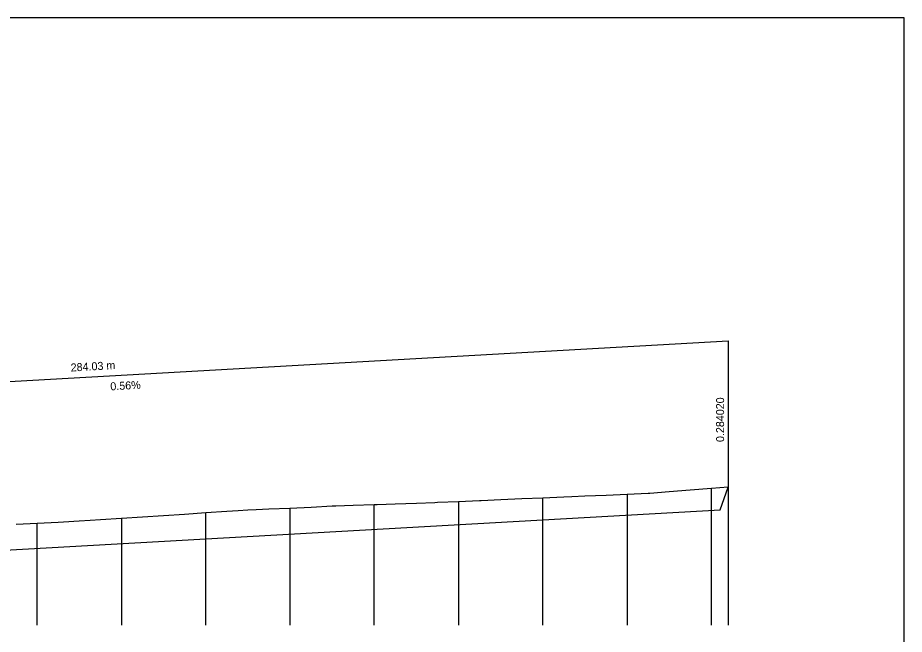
# Model space of a CAD drawing. Extents: x -495905 to -478420, y -1113297 to -1107716.
# Drawn here: x -494568.8 to -494358.5, y -1110160.5 to -1110014.2 of the extents above; entities that cross this region are included whole.
import ezdxf

# ---------------------------------------------------------------- set-up
doc = ezdxf.new("R2010")
doc.units = 0
for name, color, linetype in [('1', 7, 'Continuous'), ('2', 7, 'Continuous'), ('Implicitní', 7, 'Continuous'), ('legenda', 7, 'Continuous')]:
    doc.layers.add(name, color=color, linetype=linetype)

msp = doc.modelspace()

# ---------------------------------------------------------------- linework, layer by layer
at = {"layer": '1'}
for p, q in [((-494429.23, -1110127.56), (-494434.23, -1110127.77)), ((-494424.23, -1110127.34), (-494429.23, -1110127.56)), ((-494419.23, -1110127.12), (-494424.23, -1110127.34)), ((-494424.23, -1110127.34), (-494424.23, -1110154.39)), ((-494418.87, -1110127.11), (-494419.23, -1110127.12)), ((-494414.23, -1110126.75), (-494418.87, -1110127.11)), ((-494409.23, -1110126.36), (-494414.23, -1110126.75)), ((-494404.23, -1110125.96), (-494409.23, -1110126.36)), ((-494400.21, -1110125.65), (-494404.23, -1110125.96)), ((-494404.23, -1110154.39), (-494404.23, -1110125.96)), ((-494400.21, -1110125.65), (-494400.21, -1110154.39)), ((-494400.21, -1110125.65), (-494400.21, -1110125.65)), ((-494479.23, -1110129.65), (-494483.51, -1110129.79)), ((-494474.23, -1110129.47), (-494479.23, -1110129.65)), ((-494469.82, -1110129.32), (-494474.23, -1110129.47)), ((-494469.23, -1110129.3), (-494469.82, -1110129.32)), ((-494464.23, -1110129.08), (-494469.23, -1110129.3)), ((-494459.23, -1110128.87), (-494464.23, -1110129.08)), ((-494464.23, -1110129.08), (-494464.23, -1110154.39)), ((-494458.88, -1110128.86), (-494459.23, -1110128.87)), ((-494454.23, -1110128.65), (-494458.88, -1110128.86)), ((-494449.23, -1110128.43), (-494454.23, -1110128.65)), ((-494444.23, -1110128.21), (-494449.23, -1110128.43)), ((-494439.23, -1110127.99), (-494444.23, -1110128.21)), ((-494444.23, -1110154.39), (-494444.23, -1110128.21)), ((-494437.36, -1110127.91), (-494439.23, -1110127.99)), ((-494434.23, -1110127.77), (-494437.36, -1110127.91)), ((-494524.23, -1110131.75), (-494529.23, -1110132.08)), ((-494519.23, -1110131.42), (-494524.23, -1110131.75)), ((-494524.23, -1110154.39), (-494524.23, -1110131.75)), ((-494516.52, -1110131.24), (-494519.23, -1110131.42)), ((-494514.23, -1110131.12), (-494516.52, -1110131.24)), ((-494512.23, -1110131.02), (-494514.23, -1110131.12)), ((-494509.23, -1110130.88), (-494512.23, -1110131.02)), ((-494504.23, -1110130.65), (-494509.23, -1110130.88)), ((-494499.23, -1110130.41), (-494504.23, -1110130.65)), ((-494504.23, -1110130.65), (-494504.23, -1110154.39)), ((-494494.23, -1110130.17), (-494499.23, -1110130.41)), ((-494493.33, -1110130.14), (-494494.23, -1110130.17)), ((-494489.23, -1110129.99), (-494493.33, -1110130.14)), ((-494484.23, -1110129.81), (-494489.23, -1110129.99)), ((-494483.51, -1110129.79), (-494484.23, -1110129.81)), ((-494484.23, -1110154.39), (-494484.23, -1110129.81)), ((-494554.23, -1110133.73), (-494557.97, -1110133.97)), ((-494551.67, -1110133.57), (-494554.23, -1110133.73)), ((-494549.23, -1110133.41), (-494551.67, -1110133.57)), ((-494544.23, -1110133.08), (-494549.23, -1110133.41)), ((-494539.23, -1110132.74), (-494544.23, -1110133.08)), ((-494544.23, -1110133.08), (-494544.23, -1110154.39)), ((-494534.23, -1110132.41), (-494539.23, -1110132.74)), ((-494529.23, -1110132.08), (-494534.23, -1110132.41)), ((-494564.23, -1110134.28), (-494569.23, -1110134.52)), ((-494559.23, -1110134.03), (-494564.23, -1110134.28)), ((-494564.23, -1110154.39), (-494564.23, -1110134.28)), ((-494557.97, -1110133.97), (-494559.23, -1110134.03)), ((-494564.23, -1110158.39), (-494564.23, -1110154.39)), ((-494544.23, -1110154.39), (-494544.23, -1110158.39)), ((-494524.23, -1110158.39), (-494524.23, -1110154.39)), ((-494504.23, -1110154.39), (-494504.23, -1110158.39)), ((-494484.23, -1110158.39), (-494484.23, -1110154.39)), ((-494464.23, -1110154.39), (-494464.23, -1110158.39)), ((-494444.23, -1110158.39), (-494444.23, -1110154.39)), ((-494424.23, -1110154.39), (-494424.23, -1110158.39)), ((-494404.23, -1110158.39), (-494404.23, -1110154.39)), ((-494400.21, -1110154.39), (-494400.21, -1110158.39))]:
    msp.add_line(p, q, dxfattribs=at)
at = {"layer": '2'}
for p, q in [((-494684.23, -1110106.89), (-494400.21, -1110090.9)), ((-494400.21, -1110090.9), (-494400.21, -1110130.9))]:
    msp.add_line(p, q, dxfattribs=at)
msp.add_lwpolyline([(-494684.23, -1110146.89), (-494402.11, -1110131), (-494400.21, -1110125.65)], dxfattribs=at)
at = {"layer": 'Implicitní'}
msp.add_line((-494358.45, -1110014.17), (-494778.45, -1110014.17), dxfattribs=at)
at = {"layer": 'legenda'}
msp.add_line((-494358.45, -1110311.17), (-494358.45, -1110014.17), dxfattribs=at)

# ---------------------------------------------------------------- texts
at = {"layer": '2'}
for s, rotation, p in [('284.03 m', 3.2242, (-494556.22, -1110098.18)), ('  0.56%', 3.2242, (-494548.22, -1110102.73)), ('0.284020', 90, (-494401.21, -1110114.9))]:
    msp.add_text(s, height=1.9, rotation=rotation, dxfattribs=at).set_placement(p)

doc.saveas('drawing.dxf')
